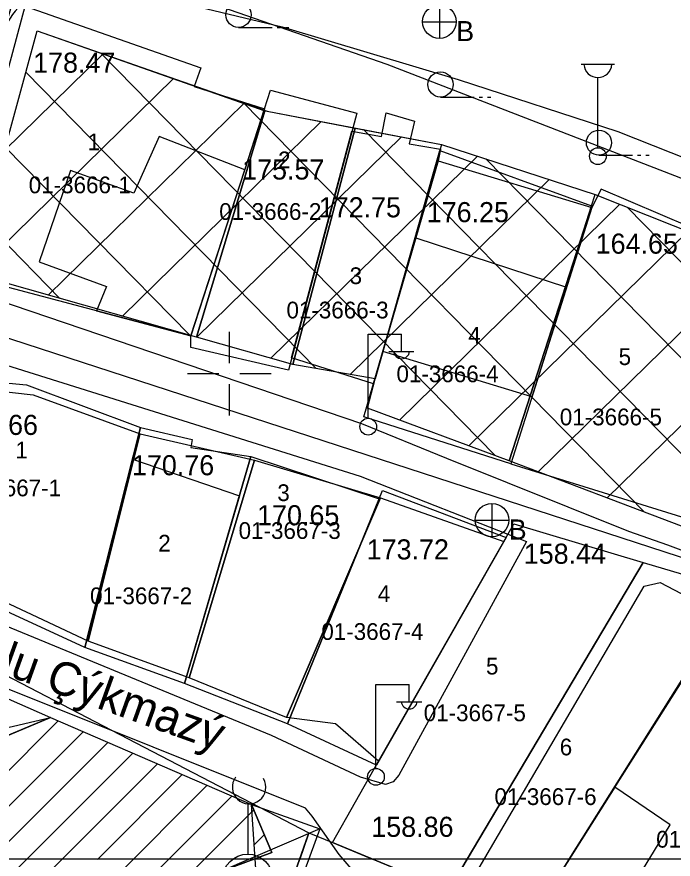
# Model space of a CAD drawing. Extents: x 419677 to 421689, y 4450851 to 4452923.
# Drawn here: x 420322.9 to 420362, y 4451756.7 to 4451807 of the extents above; entities that cross this region are included whole.
import ezdxf

# ---------------------------------------------------------------- set-up
doc = ezdxf.new("R2010")
doc.units = 0
for name, color, linetype in [('AA_HH', 7, 'Continuous'), ('Level 27', 7, 'Continuous'), ('Level 30', 7, 'Continuous'), ('Level 34', 7, 'Continuous'), ('Level 62', 7, 'Continuous'), ('Level 9', 7, 'Continuous'), ('MULKIYET SINIRI', 7, 'Continuous'), ('PARSEL KODU', 7, 'Continuous'), ('PARSEL NUMARASI', 7, 'Continuous')]:
    doc.layers.add(name, color=color, linetype=linetype)

msp = doc.modelspace()

# ---------------------------------------------------------------- linework, layer by layer
at = {"layer": 'AA_HH'}
for p, q in [((420348.078, 4451807.75), (420348.078, 4451805.75)), ((420336.085, 4451806.408), (420338.085, 4451806.408)), ((420338.385, 4451806.408), (420338.585, 4451806.408)), ((420338.885, 4451806.408), (420339.085, 4451806.408)), ((420347.078, 4451806.75), (420349.078, 4451806.75)), ((420356.539, 4451804.219), (420358.54, 4451804.219)), ((420357.54, 4451799.219), (420357.54, 4451803.412)), ((420348.143, 4451802.251), (420350.143, 4451802.251)), ((420350.443, 4451802.251), (420350.643, 4451802.251)), ((420350.943, 4451802.251), (420351.143, 4451802.251)), ((420357.6, 4451798.774), (420359.6, 4451798.774)), ((420359.9, 4451798.774), (420360.1, 4451798.774)), ((420360.4, 4451798.774), (420360.6, 4451798.774)), ((420335.535, 4451788.234), (420335.535, 4451786.359)), ((420343.82, 4451783.091), (420343.82, 4451788.091)), ((420343.82, 4451788.091), (420345.82, 4451788.091)), ((420345.82, 4451787.091), (420345.82, 4451788.091)), ((420345.06, 4451787.051), (420346.56, 4451787.051)), ((420333.035, 4451785.734), (420334.91, 4451785.734)), ((420335.535, 4451785.734), (420335.535, 4451785.734)), ((420336.16, 4451785.734), (420338.035, 4451785.734)), ((420335.535, 4451785.109), (420335.535, 4451783.234)), ((420351.215, 4451777.984), (420351.215, 4451775.984)), ((420350.215, 4451776.984), (420352.215, 4451776.984)), ((420344.28, 4451762.175), (420344.28, 4451767.175)), ((420344.28, 4451767.175), (420346.28, 4451767.175)), ((420346.28, 4451766.175), (420346.28, 4451767.175)), ((420345.52, 4451766.135), (420347.02, 4451766.135)), ((420311.677, 4451759.656), (420324.86, 4451765.194)), ((420312.707, 4451762.37), (420324.86, 4451765.194)), ((420314.143, 4451753.809), (420325.328, 4451764.991)), ((420314.772, 4451752.317), (420326.808, 4451764.35)), ((420315.401, 4451750.825), (420328.289, 4451763.709)), ((420316.03, 4451749.333), (420329.769, 4451763.069)), ((420316.659, 4451747.842), (420331.249, 4451762.428)), ((420327.658, 4451756.717), (420332.73, 4451761.787)), ((420328.223, 4451755.161), (420334.21, 4451761.146)), ((420328.597, 4451753.414), (420335.69, 4451760.505)), ((420336.638, 4451760.042), (420336.638, 4451757.036)), ((420329.753, 4451752.449), (420336.998, 4451759.692)), ((420337.581, 4451749.35), (420336.87, 4451759.995)), ((420340.935, 4451758.543), (420334.968, 4451755.986)), ((420337.048, 4451757.621), (420337.63, 4451758.203))]:
    msp.add_line(p, q, dxfattribs=at)
for points in [[(420317.857, 4451791.3), (420323.638, 4451811.627), (420344.947, 4451804.212), (420362.726, 4451797.318), (420392.528, 4451782.473), (420432.038, 4451761.332), (420447.024, 4451752.285), (420447.451, 4451751.931), (420447.78, 4451751.62), (420448.046, 4451751.251), (420448.189, 4451750.747), (420448.192, 4451750.247), (420439.685, 4451739.799), (420425.721, 4451725.725), (420414.401, 4451716.512), (420414.02, 4451716.465), (420413.266, 4451716.611), (420411.99, 4451716.077), (420403.14, 4451707.257), (420402.786, 4451706.85), (420402.646, 4451706.855), (420386.249, 4451721.836)], [(420416.094, 4451739.18), (420390.781, 4451760.073), (420376.979, 4451769.599), (420375.076, 4451770.482), (420361.716, 4451775.49), (420359.392, 4451776.308), (420348.522, 4451780.671), (420343.451, 4451782.74), (420319.477, 4451790.885)], [(420359.866, 4451743.597), (420357.268, 4451745.829), (420349.965, 4451755.409), (420360.297, 4451773.048), (420361.26, 4451773.253), (420365.056, 4451771.277)]]:
    msp.add_lwpolyline(points, dxfattribs=at)
for points in [[(420337.634, 4451801.537), (420333.243, 4451787.998), (420320.085, 4451791.473), (420321.282, 4451795.89), (420320.246, 4451796.163), (420323.345, 4451807.676), (420333.832, 4451803.998), (420333.439, 4451802.887)], [(420343.14, 4451801.278), (420339.061, 4451785.932), (420333.229, 4451787.299), (420333.243, 4451787.998), (420336.455, 4451797.9), (420337.634, 4451801.537), (420337.988, 4451802.65)], [(420342.858, 4451800.216), (420344.623, 4451799.898), (420344.908, 4451801.309), (420346.588, 4451800.816), (420346.264, 4451799.447), (420348.148, 4451799.144), (420348.004, 4451798.435), (420344.142, 4451785.126), (420339.257, 4451786.668)], [(420326.065, 4451797.855), (420324.181, 4451792.416), (420328.214, 4451790.934), (420327.605, 4451789.487), (420333.243, 4451787.998), (420336.455, 4451797.9), (420331.354, 4451799.892), (420329.837, 4451796.512)], [(420348.004, 4451798.435), (420357.18, 4451795.65), (420352.334, 4451780.351), (420343.572, 4451783.16)], [(420352.334, 4451780.351), (420362.79, 4451777.105), (420366.582, 4451792.972), (420357.734, 4451796.742), (420357.18, 4451795.65)], [(420346.671, 4451793.841), (420355.671, 4451790.886), (420353.596, 4451784.337), (420344.699, 4451787.044)], [(420353.273, 4451775.71), (420345.647, 4451761.745), (420345.314, 4451761.357), (420344.85, 4451761.194), (420343.367, 4451761.624), (420338.045, 4451764.125), (420315.118, 4451773.584), (420313.98, 4451774.162), (420313.396, 4451774.582), (420312.97, 4451774.976), (420316.7, 4451787.679), (420317.401, 4451787.755), (420343.347, 4451779.608)], [(420330.239, 4451782.519), (420326.91, 4451769.38), (420314.956, 4451774.895), (420318.18, 4451785.558), (420323.421, 4451785.058)], [(420336.827, 4451780.782), (420332.868, 4451767.228), (420326.91, 4451769.38), (420330.239, 4451782.519), (420333.31, 4451781.797), (420333.234, 4451781.324)], [(420336.827, 4451780.782), (420344.472, 4451778.246), (420339.015, 4451764.812), (420332.868, 4451767.228)], [(420329.756, 4451780.614), (420336.14, 4451778.43), (420332.868, 4451767.228), (420326.91, 4451769.38)], [(420344.674, 4451778.743), (420352.058, 4451775.946), (420344.328, 4451762.346), (420339.015, 4451764.812)], [(420365.059, 4451771.282), (420379.407, 4451762.72), (420372.701, 4451752.095), (420369.343, 4451754.114), (420362.246, 4451744.791), (420357.01, 4451749.252), (420357.26, 4451749.6), (420353.433, 4451752.963)], [(420368.825, 4451731.069), (420352.577, 4451744.745), (420342.085, 4451757.022), (420340.487, 4451759.313), (420340.084, 4451759.786), (420312.877, 4451770.67), (420311.903, 4451770.783), (420311.344, 4451770.783), (420310.92, 4451770.638), (420310.405, 4451769.578), (420305.16, 4451753.435), (420297.139, 4451728.728), (420297.073, 4451728.551), (420297.078, 4451727.532), (420297.175, 4451726.291), (420297.316, 4451725.747), (420298.05, 4451725.043), (420325.617, 4451715.521), (420335.427, 4451711.646), (420374.93, 4451696.778), (420388.99, 4451690.042), (420401.401, 4451703.801), (420392.23, 4451711.812), (420378.388, 4451723.074)], [(420311.677, 4451759.656), (420312.707, 4451762.37), (420317.754, 4451768.331), (420324.86, 4451765.194)], [(420311.677, 4451759.656), (420324.86, 4451765.194), (420336.87, 4451759.995), (420338.084, 4451757.132), (420334.968, 4451755.986), (420337.581, 4451749.35), (420335.797, 4451744.768), (420332.36, 4451743.398), (420332.44, 4451742.866), (420327.844, 4451740.871), (420327.703, 4451741.307), (420322.845, 4451739.759), (420320.895, 4451740.484), (420319.561, 4451740.961)], [(420354.708, 4451754.972), (420358.103, 4451752.651), (420361.858, 4451758.789), (420358.558, 4451761.038)], [(420340.935, 4451758.543), (420337.581, 4451749.35), (420334.968, 4451755.986), (420338.084, 4451757.132), (420336.87, 4451759.995)]]:
    msp.add_lwpolyline(points, close=True, dxfattribs=at)
for centre, radius in [((420336.085, 4451807.158), 0.75), ((420348.078, 4451806.75), 1), ((420348.143, 4451803.001), 0.75), ((420357.6, 4451799.524), 0.75), ((420357.54, 4451798.719), 0.5), ((420343.83, 4451782.566), 0.5), ((420351.215, 4451776.984), 1), ((420344.29, 4451761.651), 0.5), ((420336.638, 4451755.536), 1.5)]:
    msp.add_circle(centre, radius, dxfattribs=at)
for centre, radius, start, end in [((420357.54, 4451804.249), 0.837, 183.298, 356.9072), ((420345.82, 4451787.094), 0.474, 184.8384, 355.1464), ((420346.28, 4451766.179), 0.474, 184.8384, 355.1464), ((420336.716, 4451761.039), 1, 143.6021, 30.4889)]:
    msp.add_arc(centre, radius, start, end, dxfattribs=at)
at = {"layer": 'Level 27'}
for points in [[(420397.113, 4451756.74), (420392.92, 4451760.22), (420385.899, 4451766.103), (420377.26, 4451771.14), (420369.31, 4451775.24), (420362.52, 4451776.62), (420352.25, 4451780.53), (420343.79, 4451783.66), (420344.244, 4451785.412), (420339.32, 4451786.28), (420333.57, 4451787.91), (420320.1, 4451791.729), (420324.065, 4451806.195)], [(420423.195, 4451733.277), (420418.728, 4451738.507), (420412.135, 4451744.633), (420405.26, 4451749.98), (420392.92, 4451760.22), (420385.899, 4451766.103), (420377.26, 4451771.14), (420369.31, 4451775.24), (420362.52, 4451776.62), (420352.25, 4451780.53), (420343.79, 4451783.66), (420344.244, 4451785.412), (420339.32, 4451786.28), (420333.57, 4451787.91), (420320.1, 4451791.729), (420324.065, 4451806.195)], [(420324.065, 4451806.195), (420337.8, 4451801.4), (420348.207, 4451799.414), (420357.368, 4451796.427), (420366.68, 4451792.73), (420374.06, 4451789.53), (420383.82, 4451784.7), (420392.31, 4451779.92), (420399.99, 4451775.79), (420416.545, 4451766.613), (420424.449, 4451762.266), (420432.889, 4451757.056), (420433.505, 4451756.74)], [(420324.065, 4451806.195), (420337.8, 4451801.4), (420348.207, 4451799.414), (420357.368, 4451796.427), (420366.68, 4451792.73), (420374.06, 4451789.53), (420383.82, 4451784.7), (420392.31, 4451779.92), (420399.99, 4451775.79), (420416.545, 4451766.613), (420424.449, 4451762.266), (420432.889, 4451757.056), (420441.004, 4451752.895)]]:
    msp.add_lwpolyline(points, dxfattribs=at)
at = {"layer": 'Level 30'}
msp.add_arc((420280.492, 4451625.321), 200, 63.0091, 82.97918, dxfattribs=at)
msp.add_arc((420280.492, 4451625.321), 200, 63.0091, 82.97918, dxfattribs=at)
at = {"layer": 'Level 34'}
for p, q in [((420322.107, 4451799.052), (420327.997, 4451804.822)), ((420322.107, 4451799.052), (420327.997, 4451804.822)), ((420351.409, 4451780.841), (420327.871, 4451804.866)), ((420351.409, 4451780.841), (420327.871, 4451804.866)), ((420320.292, 4451791.674), (420332.211, 4451803.351)), ((420320.292, 4451791.674), (420332.211, 4451803.351)), ((420340.723, 4451786.033), (420323.388, 4451803.726)), ((420340.723, 4451786.033), (420323.388, 4451803.726)), ((420324.725, 4451790.418), (420336.425, 4451801.88)), ((420324.725, 4451790.418), (420336.425, 4451801.88)), ((420360.326, 4451777.455), (420336.381, 4451801.895)), ((420360.326, 4451777.455), (420336.381, 4451801.895)), ((420329.158, 4451789.161), (420341.023, 4451800.785)), ((420329.158, 4451789.161), (420341.023, 4451800.785)), ((420367.795, 4451775.548), (420343.54, 4451800.305)), ((420367.795, 4451775.548), (420343.54, 4451800.305)), ((420333.591, 4451787.904), (420345.807, 4451799.872)), ((420333.591, 4451787.904), (420345.807, 4451799.872)), ((420333.174, 4451788.022), (420322.164, 4451799.26)), ((420333.174, 4451788.022), (420322.164, 4451799.26)), ((420338.024, 4451786.647), (420350.344, 4451798.717)), ((420338.024, 4451786.647), (420350.344, 4451798.717)), ((420378.317, 4451770.524), (420350.859, 4451798.549)), ((420378.317, 4451770.524), (420350.859, 4451798.549)), ((420342.748, 4451785.676), (420354.632, 4451797.319)), ((420342.748, 4451785.676), (420354.632, 4451797.319)), ((420345.689, 4451782.957), (420358.84, 4451795.842)), ((420345.689, 4451782.957), (420358.84, 4451795.842)), ((420397.421, 4451756.74), (420359.283, 4451795.667)), ((420398.759, 4451755.375), (420359.283, 4451795.667)), ((420325.42, 4451790.221), (420320.94, 4451794.794)), ((420325.42, 4451790.221), (420320.94, 4451794.794)), ((420349.838, 4451781.422), (420362.908, 4451794.228)), ((420349.838, 4451781.422), (420362.908, 4451794.228)), ((420353.973, 4451779.874), (420366.968, 4451792.605)), ((420353.973, 4451779.874), (420366.968, 4451792.605)), ((420358.089, 4451778.307), (420370.93, 4451790.887)), ((420358.089, 4451778.307), (420370.93, 4451790.887))]:
    msp.add_line(p, q, dxfattribs=at)
at = {"layer": 'Level 62'}
msp.add_lwpolyline([(420328.286, 4451808.958), (420338.698, 4451806.448), (420349.206, 4451803.296), (420358.727, 4451800.191), (420368.214, 4451796.425), (420375.744, 4451793.16), (420385.69, 4451788.238), (420394.239, 4451783.425), (420401.907, 4451779.301), (420418.478, 4451770.115), (420426.465, 4451765.722), (420434.903, 4451761.025), (420440.151, 4451757.998)], dxfattribs=at)
msp.add_lwpolyline([(420328.286, 4451808.958), (420338.698, 4451806.448), (420349.206, 4451803.296), (420358.727, 4451800.191), (420368.214, 4451796.425), (420375.744, 4451793.16), (420385.69, 4451788.238), (420394.239, 4451783.425), (420401.907, 4451779.301), (420418.478, 4451770.115), (420426.465, 4451765.722), (420434.903, 4451761.025), (420440.151, 4451757.998)], dxfattribs=at)
msp.add_arc((420326.639, 4451804.237), 5, 70.7591, 164.6724, dxfattribs=at)
msp.add_arc((420326.639, 4451804.237), 5, 70.7591, 164.6724, dxfattribs=at)
at = {"layer": 'Level 9'}
msp.add_line((420369.24, 4451772.561), (420313.771, 4451790.624), dxfattribs=at)
msp.add_line((420369.24, 4451772.561), (420313.771, 4451790.624), dxfattribs=at)
at = {"layer": 'MULKIYET SINIRI'}
for points in [[(420320.1, 4451791.729), (420324.065, 4451806.195), (420337.653, 4451801.428), (420333.57, 4451787.91)], [(420320.1, 4451791.729), (420324.065, 4451806.195), (420337.653, 4451801.428), (420333.57, 4451787.91)], [(420333.57, 4451787.91), (420337.653, 4451801.428), (420337.8, 4451801.4), (420343.04, 4451800.4), (420339.32, 4451786.28)], [(420333.57, 4451787.91), (420337.653, 4451801.428), (420337.8, 4451801.4), (420343.04, 4451800.4), (420339.32, 4451786.28)], [(420339.32, 4451786.28), (420343.04, 4451800.4), (420348.207, 4451799.414), (420348.108, 4451799.065), (420347.705, 4451797.654), (420344.244, 4451785.412)], [(420339.32, 4451786.28), (420343.04, 4451800.4), (420348.207, 4451799.414), (420348.108, 4451799.065), (420347.705, 4451797.654), (420344.244, 4451785.412)], [(420343.79, 4451783.66), (420344.244, 4451785.412), (420347.705, 4451797.654), (420348.108, 4451799.065), (420357.154, 4451795.76), (420356.69, 4451794.319), (420352.25, 4451780.53)], [(420343.79, 4451783.66), (420344.244, 4451785.412), (420347.705, 4451797.654), (420348.108, 4451799.065), (420357.154, 4451795.76), (420356.69, 4451794.319), (420352.25, 4451780.53)], [(420352.25, 4451780.53), (420356.69, 4451794.319), (420357.154, 4451795.76), (420357.368, 4451796.427), (420366.68, 4451792.73), (420362.52, 4451776.62)], [(420352.25, 4451780.53), (420356.69, 4451794.319), (420357.154, 4451795.76), (420357.368, 4451796.427), (420366.68, 4451792.73), (420362.52, 4451776.62)], [(420315.7, 4451775.1), (420318.54, 4451785.06), (420323.83, 4451784.46), (420330.205, 4451782.128), (420330.18, 4451782.03), (420327.11, 4451769.76)], [(420315.7, 4451775.1), (420318.54, 4451785.06), (420323.83, 4451784.46), (420330.205, 4451782.128), (420330.18, 4451782.03), (420327.11, 4451769.76)], [(420327.11, 4451769.76), (420330.18, 4451782.03), (420330.205, 4451782.128), (420337.04, 4451780.56), (420333.14, 4451767.57)], [(420327.11, 4451769.76), (420330.18, 4451782.03), (420330.205, 4451782.128), (420337.04, 4451780.56), (420333.14, 4451767.57)], [(420333.14, 4451767.57), (420337.04, 4451780.56), (420344.57, 4451778.32), (420338.95, 4451765.19)], [(420333.14, 4451767.57), (420337.04, 4451780.56), (420344.57, 4451778.32), (420338.95, 4451765.19)], [(420338.95, 4451765.19), (420344.57, 4451778.32), (420351.92, 4451775.71), (420344.45, 4451762.58), (420341.867, 4451764.821)], [(420338.95, 4451765.19), (420344.57, 4451778.32), (420351.92, 4451775.71), (420344.45, 4451762.58), (420341.867, 4451764.821)], [(420341.69, 4451757.728), (420344.45, 4451762.58), (420351.92, 4451775.71), (420352.513, 4451776.753), (420360.248, 4451774.452), (420348.724, 4451755.025), (420346.307, 4451755.822)], [(420348.724, 4451755.025), (420360.248, 4451774.452), (420365.807, 4451772.798), (420364.8, 4451770.95), (420363.91, 4451769.64), (420362.66, 4451767.63), (420353.71, 4451753.38)], [(420353.71, 4451753.38), (420362.66, 4451767.63), (420363.91, 4451769.64), (420364.8, 4451770.95), (420379.3, 4451762.54), (420372.385, 4451752.114), (420369.52, 4451753.83), (420367.73, 4451751.62), (420367.38, 4451751.16), (420365.606, 4451748.803), (420362.419, 4451744.568), (420361.55, 4451745.51)], [(420312.502, 4451750.433), (420315.174, 4451755.568), (420321.647, 4451768.009), (420328.011, 4451764.697), (420340.278, 4451758.312), (420340.23, 4451758.13), (420338.48, 4451753.15), (420337.82, 4451751.61), (420336.42, 4451747.84), (420336.4, 4451747.54), (420334.48, 4451742.68), (420323.73, 4451746.39), (420322.37, 4451746.94), (420314.48, 4451749.69)], [(420336.4, 4451747.54), (420336.42, 4451747.84), (420337.82, 4451751.61), (420338.48, 4451753.15), (420340.23, 4451758.13), (420340.278, 4451758.312), (420341.69, 4451757.728), (420346.307, 4451755.822), (420344, 4451751.084), (420343.28, 4451749.52), (420342.33, 4451747.54), (420341.85, 4451746.794), (420341.291, 4451745.927)]]:
    msp.add_lwpolyline(points, close=True, dxfattribs=at)
for points in [[(420344.083, 4451756.74), (420341.69, 4451757.728), (420344.45, 4451762.58), (420351.92, 4451775.71), (420352.513, 4451776.753), (420360.248, 4451774.452), (420349.741, 4451756.74)], [(420349.741, 4451756.74), (420360.248, 4451774.452), (420365.807, 4451772.798), (420364.8, 4451770.95), (420363.91, 4451769.64), (420362.66, 4451767.63), (420355.82, 4451756.74)], [(420355.82, 4451756.74), (420362.66, 4451767.63), (420363.91, 4451769.64), (420364.8, 4451770.95), (420379.3, 4451762.54), (420375.453, 4451756.74)], [(420315.784, 4451756.74), (420321.647, 4451768.009), (420328.011, 4451764.697), (420340.278, 4451758.312), (420340.23, 4451758.13), (420339.742, 4451756.74)], [(420339.742, 4451756.74), (420340.23, 4451758.13), (420340.278, 4451758.312), (420341.69, 4451757.728), (420344.083, 4451756.74)], [(420339.742, 4451756.74), (420315.784, 4451756.74)], [(420344.083, 4451756.74), (420339.742, 4451756.74)], [(420349.741, 4451756.74), (420344.083, 4451756.74)], [(420355.82, 4451756.74), (420349.741, 4451756.74)], [(420375.453, 4451756.74), (420355.82, 4451756.74)]]:
    msp.add_lwpolyline(points, dxfattribs=at)

# ---------------------------------------------------------------- texts
at = {"layer": 'AA_HH'}
for s, p in [('B', (420349.078, 4451805.589)), ('178.47', (420323.825, 4451803.703)), ('175.57', (420336.304, 4451797.321)), ('172.75', (420340.875, 4451795.064)), ('176.25', (420347.322, 4451794.776)), ('164.65', (420357.406, 4451792.895)), ('173.66', (420319.207, 4451782.071)), ('170.76', (420329.724, 4451779.662)), ('170.65', (420337.196, 4451776.675)), ('B', (420352.215, 4451775.823)), ('173.72', (420343.736, 4451774.636))]:
    msp.add_text(s, height=1.2, dxfattribs=at).set_placement(p)
for s, height, rotation, p in [('158.44 ', 1.2, 359.9981, (420353.114, 4451774.378)), ('Ulu Çýkmazý', 2, 340.2057, (420319.999, 4451768.507)), ('158.86 ', 1.2, 359.9981, (420344.011, 4451758.07))]:
    msp.add_text(s, height=height, rotation=rotation, dxfattribs=at).set_placement(p)
at = {"layer": 'PARSEL KODU'}
for s, p in [('01-3666-1', (420323.562, 4451796.502)), ('01-3666-1', (420323.562, 4451796.502)), ('01-3666-2', (420334.935, 4451794.912)), ('01-3666-2', (420334.935, 4451794.912)), ('01-3666-3', (420338.948, 4451789.029)), ('01-3666-3', (420338.948, 4451789.029)), ('01-3666-4', (420345.514, 4451785.218)), ('01-3666-4', (420345.514, 4451785.218)), ('01-3666-5', (420355.265, 4451782.644)), ('01-3666-5', (420355.265, 4451782.644)), ('01-3667-1', (420319.395, 4451778.405)), ('01-3667-1', (420319.395, 4451778.405)), ('01-3667-3', (420336.091, 4451775.86)), ('01-3667-3', (420336.091, 4451775.86)), ('01-3667-2', (420327.223, 4451771.964)), ('01-3667-2', (420327.223, 4451771.964)), ('01-3667-4', (420341.029, 4451769.829)), ('01-3667-4', (420341.029, 4451769.829)), ('01-3667-5', (420347.142, 4451764.975)), ('01-3667-5', (420347.142, 4451764.975)), ('01-3667-6', (420351.364, 4451759.97)), ('01-3667-6', (420351.364, 4451759.97)), ('01-3667-7', (420361.021, 4451757.424)), ('01-3667-7', (420361.021, 4451757.424))]:
    msp.add_text(s, height=1, dxfattribs=at).set_placement(p)
at = {"layer": 'PARSEL NUMARASI'}
for s, p in [('1', (420327.074, 4451799.068)), ('1', (420327.074, 4451799.068)), ('2', (420338.448, 4451797.995)), ('2', (420338.448, 4451797.995)), ('3', (420342.718, 4451791.078)), ('3', (420342.718, 4451791.078)), ('4', (420349.8, 4451787.526)), ('4', (420349.8, 4451787.526)), ('5', (420358.777, 4451786.243)), ('5', (420358.777, 4451786.243)), ('1', (420322.764, 4451780.667)), ('1', (420322.764, 4451780.667)), ('3', (420338.401, 4451778.121)), ('3', (420338.401, 4451778.121)), ('2', (420331.293, 4451775.105)), ('2', (420331.293, 4451775.105)), ('4', (420344.396, 4451772.09)), ('4', (420344.396, 4451772.09)), ('5', (420350.86, 4451767.764)), ('5', (420350.86, 4451767.764)), ('6', (420355.261, 4451762.935)), ('6', (420355.261, 4451762.935))]:
    msp.add_text(s, height=1, dxfattribs=at).set_placement(p)

doc.saveas('drawing.dxf')
